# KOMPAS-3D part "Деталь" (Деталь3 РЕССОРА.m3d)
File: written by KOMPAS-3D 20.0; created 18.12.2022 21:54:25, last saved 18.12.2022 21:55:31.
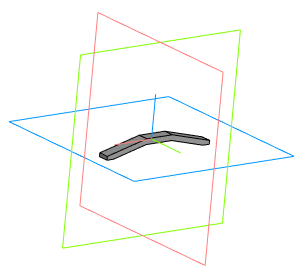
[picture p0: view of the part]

Document properties: Полное имя файла: C:\Users\Семья\Desktop\ДЕТАЛИ ДЛЯ СБОРЩИКА БОРЩЕВИКА\Деталь3 РЕССОРА.m3d

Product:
- Part/product: Деталь
    Масса: 0.0011077

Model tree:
1. Эскиз:1
2. Элемент выдавливания:1
     Расстояние 1 = 3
